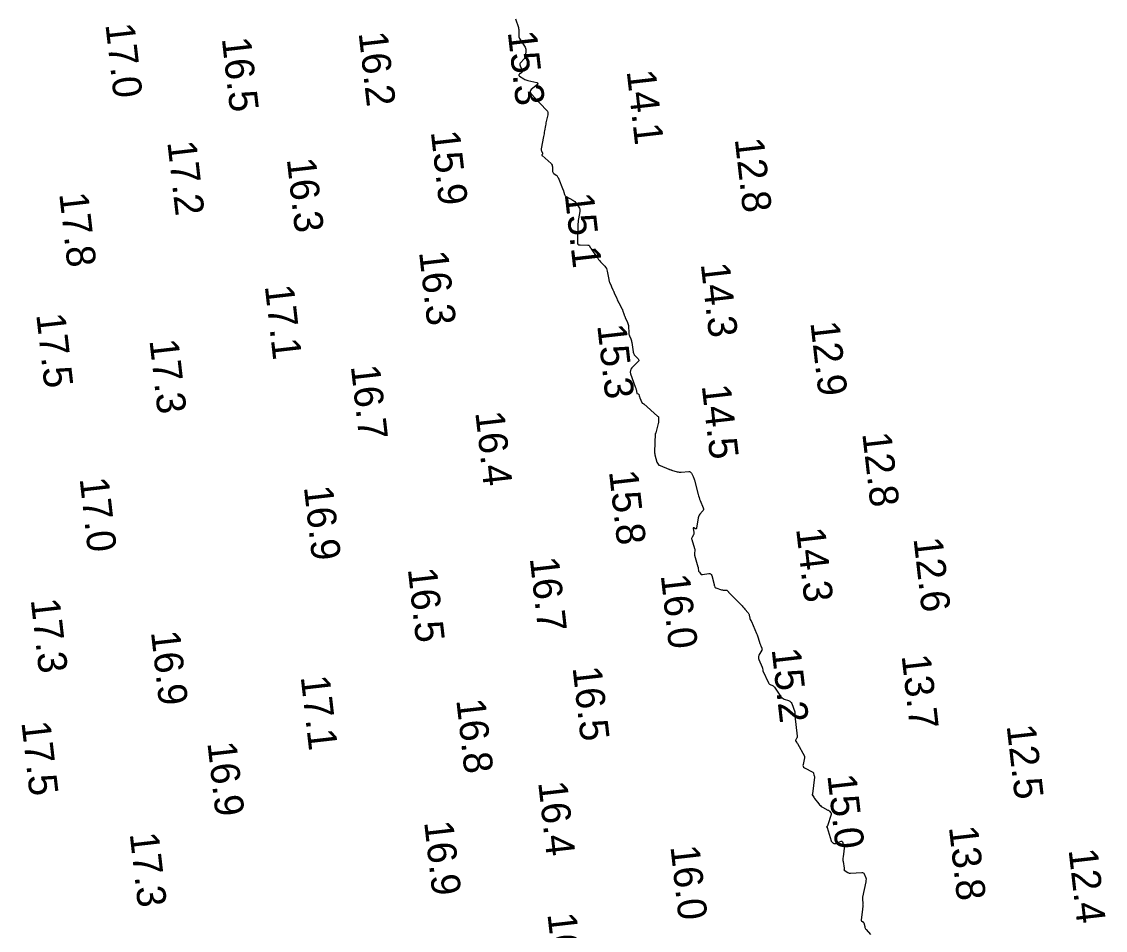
# Model space of a CAD drawing. Extents: x 1023796 to 1112670, y 656573 to 837340.
# Drawn here: x 1110573.1 to 1110760.3, y 679399.9 to 679556.8 of the extents above; entities that cross this region are included whole.
import ezdxf

# ---------------------------------------------------------------- set-up
doc = ezdxf.new("R2010")
doc.units = 0
doc.layers.add('V-CHAN-CONT-15FT', color=7, linetype='Continuous')
doc.layers.add('V-TOPO-SOUN', color=7, linetype='Continuous')

msp = doc.modelspace()

# ---------------------------------------------------------------- linework, layer by layer
at = {"layer": 'V-CHAN-CONT-15FT'}
msp.add_lwpolyline([(1110658.4, 679557.31), (1110658.91, 679555.84), (1110658.96, 679555.67), (1110659, 679555.5), (1110659.01, 679555.32), (1110659.02, 679555.14), (1110659, 679554.42), (1110659.01, 679554.25), (1110659.04, 679554.08), (1110659.11, 679553.92), (1110659.2, 679553.77), (1110660, 679552.63), (1110660.1, 679552.45), (1110660.17, 679552.27), (1110660.21, 679552.07), (1110660.22, 679551.87), (1110660.17, 679550.99), (1110660.15, 679550.81), (1110660.09, 679550.64), (1110660, 679550.49), (1110659.88, 679550.35), (1110659.34, 679549.82), (1110659.23, 679549.68), (1110659.18, 679549.54), (1110659.17, 679549.38), (1110659.22, 679549.22), (1110659.58, 679548.44), (1110659.61, 679548.33), (1110659.61, 679548.23), (1110659.57, 679548.14), (1110659.49, 679548.06), (1110659.09, 679547.75), (1110659.01, 679547.67), (1110658.99, 679547.6), (1110659.02, 679547.53), (1110659.1, 679547.46), (1110659.85, 679546.98), (1110660.01, 679546.88), (1110660.18, 679546.8), (1110660.36, 679546.74), (1110660.54, 679546.69), (1110662.08, 679546.35), (1110662.11, 679546.34), (1110662.14, 679546.32), (1110662.17, 679546.3), (1110662.19, 679546.26), (1110662.25, 679546.12), (1110662.26, 679546.09), (1110662.26, 679546.06), (1110662.24, 679546.03), (1110662.22, 679546), (1110661.14, 679545.13), (1110661, 679544.97), (1110660.94, 679544.81), (1110660.97, 679544.64), (1110661.09, 679544.46), (1110661.95, 679543.5), (1110662.15, 679543.28), (1110662.35, 679543.06), (1110662.55, 679542.85), (1110662.75, 679542.63), (1110663.79, 679541.54), (1110663.92, 679541.36), (1110664, 679541.17), (1110664.03, 679540.97), (1110664, 679540.75), (1110663.78, 679539.84), (1110663.73, 679539.61), (1110663.68, 679539.39), (1110663.63, 679539.16), (1110663.59, 679538.93), (1110663.43, 679537.97), (1110663.39, 679537.74), (1110663.35, 679537.5), (1110663.31, 679537.27), (1110663.26, 679537.03), (1110662.86, 679534.89), (1110662.85, 679534.8), (1110662.85, 679534.71), (1110662.87, 679534.63), (1110662.9, 679534.54), (1110663.09, 679534.12), (1110663.11, 679534.08), (1110663.11, 679534.05), (1110663.1, 679534.01), (1110663.08, 679533.98), (1110662.98, 679533.85), (1110662.97, 679533.82), (1110662.96, 679533.79), (1110662.97, 679533.76), (1110663, 679533.74), (1110664.55, 679532.34), (1110664.65, 679532.22), (1110664.73, 679532.09), (1110664.78, 679531.94), (1110664.8, 679531.79), (1110664.81, 679531.06), (1110664.82, 679530.94), (1110664.87, 679530.83), (1110664.93, 679530.73), (1110665.03, 679530.65), (1110665.45, 679530.35), (1110665.55, 679530.27), (1110665.63, 679530.17), (1110665.7, 679530.07), (1110665.76, 679529.96), (1110666.64, 679527.76), (1110666.68, 679527.67), (1110666.72, 679527.57), (1110666.75, 679527.47), (1110666.78, 679527.37), (1110666.9, 679526.97), (1110666.94, 679526.87), (1110666.99, 679526.79), (1110667.06, 679526.72), (1110667.15, 679526.66), (1110668.32, 679525.99), (1110668.49, 679525.88), (1110668.64, 679525.76), (1110668.78, 679525.61), (1110668.9, 679525.46), (1110669.36, 679524.8), (1110669.45, 679524.63), (1110669.51, 679524.45), (1110669.54, 679524.27), (1110669.52, 679524.07), (1110669.3, 679522.77), (1110669.26, 679522.49), (1110669.22, 679522.2), (1110669.2, 679521.92), (1110669.19, 679521.63), (1110669.1, 679518.8), (1110669.12, 679518.58), (1110669.21, 679518.42), (1110669.37, 679518.32), (1110669.58, 679518.29), (1110670.93, 679518.26), (1110671.01, 679518.25), (1110671.07, 679518.23), (1110671.12, 679518.19), (1110671.17, 679518.13), (1110671.34, 679517.87), (1110671.38, 679517.8), (1110671.42, 679517.74), (1110671.46, 679517.68), (1110671.51, 679517.61), (1110672.47, 679516.2), (1110672.62, 679515.99), (1110672.78, 679515.78), (1110672.94, 679515.58), (1110673.12, 679515.39), (1110673.83, 679514.63), (1110673.99, 679514.44), (1110674.12, 679514.22), (1110674.21, 679513.99), (1110674.27, 679513.75), (1110674.51, 679512.34), (1110674.54, 679512.22), (1110674.57, 679512.1), (1110674.61, 679511.98), (1110674.65, 679511.87), (1110674.89, 679511.33), (1110674.92, 679511.26), (1110674.95, 679511.19), (1110674.98, 679511.13), (1110675.01, 679511.06), (1110675.14, 679510.77), (1110675.17, 679510.71), (1110675.19, 679510.65), (1110675.22, 679510.59), (1110675.25, 679510.53), (1110675.36, 679510.28), (1110675.39, 679510.22), (1110675.41, 679510.15), (1110675.44, 679510.09), (1110675.47, 679510.03), (1110675.9, 679509.02), (1110675.98, 679508.83), (1110676.07, 679508.65), (1110676.16, 679508.46), (1110676.25, 679508.28), (1110676.82, 679507.21), (1110676.87, 679507.12), (1110676.91, 679507.03), (1110676.95, 679506.93), (1110676.98, 679506.84), (1110677.12, 679506.37), (1110677.14, 679506.31), (1110677.16, 679506.26), (1110677.18, 679506.21), (1110677.2, 679506.15), (1110677.28, 679505.95), (1110677.3, 679505.89), (1110677.33, 679505.84), (1110677.35, 679505.79), (1110677.37, 679505.74), (1110677.77, 679504.88), (1110677.83, 679504.72), (1110677.88, 679504.55), (1110677.91, 679504.38), (1110677.93, 679504.21), (1110677.97, 679503.18), (1110677.99, 679503.03), (1110678.01, 679502.88), (1110678.05, 679502.74), (1110678.1, 679502.6), (1110678.33, 679502.04), (1110678.38, 679501.9), (1110678.43, 679501.75), (1110678.46, 679501.61), (1110678.49, 679501.46), (1110678.72, 679499.85), (1110678.73, 679499.79), (1110678.74, 679499.72), (1110678.77, 679499.66), (1110678.79, 679499.6), (1110678.91, 679499.36), (1110678.94, 679499.3), (1110678.97, 679499.24), (1110679.01, 679499.19), (1110679.06, 679499.14), (1110679.6, 679498.61), (1110679.68, 679498.5), (1110679.71, 679498.39), (1110679.69, 679498.29), (1110679.61, 679498.18), (1110678.53, 679497.07), (1110678.35, 679496.84), (1110678.26, 679496.59), (1110678.24, 679496.33), (1110678.3, 679496.05), (1110679.11, 679493.78), (1110679.15, 679493.67), (1110679.18, 679493.56), (1110679.21, 679493.44), (1110679.24, 679493.32), (1110679.35, 679492.68), (1110679.37, 679492.65), (1110679.38, 679492.62), (1110679.41, 679492.61), (1110679.44, 679492.6), (1110679.59, 679492.57), (1110679.62, 679492.56), (1110679.65, 679492.54), (1110679.67, 679492.52), (1110679.69, 679492.49), (1110679.8, 679492.16), (1110679.82, 679492.09), (1110679.84, 679492.03), (1110679.87, 679491.96), (1110679.9, 679491.89), (1110680.24, 679491.05), (1110680.25, 679491.02), (1110680.27, 679491), (1110680.3, 679490.98), (1110680.32, 679490.97), (1110680.45, 679490.92), (1110680.47, 679490.91), (1110680.5, 679490.89), (1110680.53, 679490.87), (1110680.56, 679490.85), (1110682.96, 679488.74), (1110683.03, 679488.66), (1110683.09, 679488.57), (1110683.12, 679488.47), (1110683.13, 679488.36), (1110683.12, 679487.9), (1110683.12, 679487.79), (1110683.11, 679487.67), (1110683.09, 679487.56), (1110683.07, 679487.45), (1110682.67, 679485.82), (1110682.66, 679485.8), (1110682.65, 679485.79), (1110682.64, 679485.77), (1110682.63, 679485.76), (1110682.57, 679485.71), (1110682.56, 679485.69), (1110682.55, 679485.68), (1110682.54, 679485.66), (1110682.54, 679485.64), (1110682.42, 679482.55), (1110682.42, 679482.52), (1110682.42, 679482.5), (1110682.42, 679482.47), (1110682.42, 679482.44), (1110682.43, 679482.29), (1110682.43, 679482.28), (1110682.43, 679482.28), (1110682.44, 679482.28), (1110682.44, 679482.27), (1110682.46, 679482.26), (1110682.47, 679482.25), (1110682.47, 679482.25), (1110682.47, 679482.24), (1110682.47, 679482.24), (1110682.49, 679482.13), (1110682.5, 679482.11), (1110682.5, 679482.09), (1110682.51, 679482.07), (1110682.51, 679482.05), (1110682.85, 679480.78), (1110682.93, 679480.58), (1110683.04, 679480.41), (1110683.2, 679480.27), (1110683.39, 679480.17), (1110684.91, 679479.56), (1110684.95, 679479.54), (1110684.99, 679479.53), (1110685.02, 679479.52), (1110685.06, 679479.5), (1110685.23, 679479.46), (1110685.27, 679479.45), (1110685.31, 679479.44), (1110685.35, 679479.43), (1110685.38, 679479.41), (1110686.34, 679479.12), (1110686.52, 679479.08), (1110686.69, 679479.05), (1110686.87, 679479.04), (1110687.05, 679479.04), (1110688.33, 679479.14), (1110688.48, 679479.13), (1110688.61, 679479.09), (1110688.72, 679479), (1110688.8, 679478.87), (1110689.09, 679478.29), (1110689.16, 679478.14), (1110689.22, 679477.99), (1110689.27, 679477.84), (1110689.32, 679477.68), (1110689.96, 679475.21), (1110690.04, 679474.93), (1110690.12, 679474.66), (1110690.22, 679474.4), (1110690.32, 679474.13), (1110690.84, 679472.89), (1110690.89, 679472.73), (1110690.88, 679472.58), (1110690.84, 679472.43), (1110690.74, 679472.3), (1110690.26, 679471.76), (1110690.15, 679471.62), (1110690.06, 679471.47), (1110690, 679471.31), (1110689.96, 679471.14), (1110689.68, 679469.37), (1110689.66, 679469.3), (1110689.62, 679469.26), (1110689.57, 679469.25), (1110689.5, 679469.27), (1110689.2, 679469.42), (1110689.13, 679469.44), (1110689.09, 679469.43), (1110689.08, 679469.39), (1110689.08, 679469.33), (1110689.22, 679468.65), (1110689.23, 679468.53), (1110689.22, 679468.43), (1110689.2, 679468.32), (1110689.15, 679468.22), (1110688.91, 679467.81), (1110688.87, 679467.71), (1110688.84, 679467.61), (1110688.84, 679467.5), (1110688.87, 679467.39), (1110689.35, 679465.85), (1110689.37, 679465.76), (1110689.38, 679465.66), (1110689.39, 679465.57), (1110689.38, 679465.47), (1110689.33, 679465.09), (1110689.32, 679465), (1110689.32, 679464.9), (1110689.33, 679464.81), (1110689.35, 679464.71), (1110689.92, 679462.68), (1110689.94, 679462.61), (1110689.95, 679462.54), (1110689.96, 679462.47), (1110689.97, 679462.4), (1110690, 679462.03), (1110690.01, 679462), (1110690.01, 679461.97), (1110690.03, 679461.95), (1110690.04, 679461.93), (1110690.12, 679461.84), (1110690.16, 679461.8), (1110690.19, 679461.75), (1110690.45, 679461.44), (1110690.5, 679461.39), (1110690.56, 679461.36), (1110690.63, 679461.35), (1110690.7, 679461.35), (1110691.78, 679461.51), (1110691.97, 679461.52), (1110692.12, 679461.46), (1110692.23, 679461.34), (1110692.3, 679461.17), (1110692.7, 679459.63), (1110692.71, 679459.57), (1110692.73, 679459.52), (1110692.75, 679459.46), (1110692.77, 679459.4), (1110692.87, 679459.19), (1110692.9, 679459.14), (1110692.93, 679459.1), (1110692.98, 679459.06), (1110693.03, 679459.04), (1110694.02, 679458.73), (1110694.11, 679458.7), (1110694.19, 679458.69), (1110694.28, 679458.68), (1110694.37, 679458.68), (1110694.8, 679458.68), (1110694.84, 679458.68), (1110694.89, 679458.66), (1110694.93, 679458.64), (1110694.96, 679458.61), (1110695.09, 679458.47), (1110695.13, 679458.43), (1110695.16, 679458.39), (1110695.2, 679458.36), (1110695.23, 679458.32), (1110697.56, 679455.95), (1110697.68, 679455.81), (1110697.81, 679455.68), (1110697.93, 679455.54), (1110698.05, 679455.4), (1110698.61, 679454.72), (1110698.67, 679454.64), (1110698.72, 679454.55), (1110698.75, 679454.45), (1110698.78, 679454.35), (1110698.88, 679453.83), (1110698.89, 679453.78), (1110698.9, 679453.72), (1110698.93, 679453.67), (1110698.95, 679453.62), (1110699.06, 679453.42), (1110699.09, 679453.37), (1110699.11, 679453.32), (1110699.14, 679453.27), (1110699.16, 679453.22), (1110700.06, 679451.16), (1110700.14, 679450.97), (1110700.21, 679450.78), (1110700.28, 679450.59), (1110700.34, 679450.4), (1110700.64, 679449.44), (1110700.67, 679449.34), (1110700.71, 679449.24), (1110700.74, 679449.14), (1110700.78, 679449.04), (1110700.95, 679448.65), (1110700.98, 679448.56), (1110700.99, 679448.46), (1110700.97, 679448.37), (1110700.94, 679448.28), (1110700.46, 679447.41), (1110700.39, 679447.23), (1110700.36, 679447.05), (1110700.37, 679446.87), (1110700.43, 679446.69), (1110701.02, 679445.36), (1110701.04, 679445.31), (1110701.06, 679445.25), (1110701.07, 679445.2), (1110701.08, 679445.14), (1110701.11, 679444.91), (1110701.11, 679444.86), (1110701.13, 679444.8), (1110701.14, 679444.75), (1110701.16, 679444.7), (1110702.09, 679442.65), (1110702.14, 679442.56), (1110702.21, 679442.48), (1110702.29, 679442.41), (1110702.38, 679442.36), (1110702.8, 679442.2), (1110702.9, 679442.15), (1110702.98, 679442.09), (1110703.06, 679442.02), (1110703.13, 679441.93), (1110704.21, 679440.33), (1110704.33, 679440.18), (1110704.48, 679440.04), (1110704.64, 679439.94), (1110704.82, 679439.86), (1110705.59, 679439.58), (1110705.77, 679439.5), (1110705.92, 679439.38), (1110706.03, 679439.24), (1110706.12, 679439.06), (1110706.65, 679437.65), (1110706.67, 679437.59), (1110706.68, 679437.54), (1110706.68, 679437.48), (1110706.68, 679437.42), (1110706.66, 679437.19), (1110706.65, 679437.13), (1110706.65, 679437.07), (1110706.66, 679437.01), (1110706.66, 679436.95), (1110707.08, 679433.46), (1110707.09, 679433.37), (1110707.07, 679433.29), (1110707.05, 679433.22), (1110707.01, 679433.14), (1110706.81, 679432.82), (1110706.78, 679432.77), (1110706.77, 679432.71), (1110706.78, 679432.66), (1110706.81, 679432.6), (1110706.96, 679432.39), (1110707, 679432.33), (1110707.03, 679432.28), (1110707.07, 679432.22), (1110707.1, 679432.16), (1110708.31, 679429.97), (1110708.32, 679429.95), (1110708.33, 679429.93), (1110708.33, 679429.9), (1110708.34, 679429.88), (1110708.35, 679429.78), (1110708.35, 679429.75), (1110708.35, 679429.73), (1110708.35, 679429.7), (1110708.34, 679429.68), (1110708.07, 679428.57), (1110708.05, 679428.39), (1110708.09, 679428.24), (1110708.18, 679428.11), (1110708.33, 679428), (1110709.74, 679427.24), (1110709.79, 679427.21), (1110709.84, 679427.16), (1110709.87, 679427.11), (1110709.89, 679427.04), (1110709.95, 679426.7), (1110709.96, 679426.67), (1110709.97, 679426.65), (1110709.98, 679426.62), (1110709.99, 679426.6), (1110710.05, 679426.5), (1110710.06, 679426.47), (1110710.07, 679426.45), (1110710.07, 679426.42), (1110710.07, 679426.39), (1110709.7, 679423.49), (1110709.7, 679423.48), (1110709.69, 679423.46), (1110709.69, 679423.45), (1110709.68, 679423.44), (1110709.64, 679423.38), (1110709.63, 679423.37), (1110709.63, 679423.36), (1110709.63, 679423.35), (1110709.64, 679423.34), (1110709.68, 679423.27), (1110709.7, 679423.24), (1110709.92, 679422.91), (1110709.96, 679422.85), (1110710, 679422.79), (1110710.04, 679422.74), (1110710.08, 679422.68), (1110710.78, 679421.75), (1110710.92, 679421.59), (1110711.07, 679421.45), (1110711.23, 679421.32), (1110711.41, 679421.21), (1110712.37, 679420.69), (1110712.45, 679420.64), (1110712.52, 679420.59), (1110712.59, 679420.53), (1110712.65, 679420.47), (1110712.88, 679420.2), (1110712.93, 679420.13), (1110712.95, 679420.06), (1110712.96, 679419.98), (1110712.94, 679419.9), (1110712.3, 679417.98), (1110712.29, 679417.95), (1110712.28, 679417.93), (1110712.26, 679417.9), (1110712.25, 679417.88), (1110712.15, 679417.75), (1110712.15, 679417.74), (1110712.15, 679417.74), (1110712.15, 679417.73), (1110712.16, 679417.72), (1110712.2, 679417.7), (1110712.22, 679417.7), (1110712.22, 679417.69), (1110712.23, 679417.68), (1110712.23, 679417.67), (1110712.93, 679415.39), (1110712.95, 679415.33), (1110712.98, 679415.28), (1110713.01, 679415.24), (1110713.05, 679415.19), (1110713.21, 679415.01), (1110713.25, 679414.98), (1110713.29, 679414.95), (1110713.34, 679414.94), (1110713.39, 679414.93), (1110713.61, 679414.92), (1110713.66, 679414.92), (1110713.71, 679414.92), (1110713.76, 679414.93), (1110713.81, 679414.95), (1110714.67, 679415.31), (1110714.74, 679415.32), (1110714.8, 679415.31), (1110714.84, 679415.28), (1110714.88, 679415.21), (1110715.01, 679414.79), (1110715.02, 679414.76), (1110715.04, 679414.73), (1110715.06, 679414.71), (1110715.08, 679414.69), (1110715.2, 679414.63), (1110715.22, 679414.61), (1110715.24, 679414.59), (1110715.24, 679414.57), (1110715.24, 679414.54), (1110714.98, 679412.59), (1110714.96, 679412.39), (1110714.96, 679412.19), (1110714.97, 679411.99), (1110715, 679411.79), (1110715.19, 679410.67), (1110715.19, 679410.64), (1110715.19, 679410.6), (1110715.19, 679410.57), (1110715.18, 679410.54), (1110715.15, 679410.41), (1110715.14, 679410.37), (1110715.15, 679410.35), (1110715.16, 679410.32), (1110715.19, 679410.3), (1110715.81, 679409.9), (1110715.92, 679409.84), (1110716.04, 679409.8), (1110716.17, 679409.77), (1110716.3, 679409.77), (1110718.24, 679409.89), (1110718.37, 679409.88), (1110718.48, 679409.84), (1110718.57, 679409.76), (1110718.64, 679409.65), (1110718.92, 679408.95), (1110718.94, 679408.9), (1110718.95, 679408.84), (1110718.96, 679408.79), (1110718.96, 679408.73), (1110718.94, 679408.51), (1110718.93, 679408.45), (1110718.93, 679408.4), (1110718.92, 679408.34), (1110718.91, 679408.29), (1110718.35, 679405.62), (1110718.35, 679405.6), (1110718.35, 679405.58), (1110718.35, 679405.56), (1110718.35, 679405.54), (1110718.36, 679405.46), (1110718.36, 679405.44), (1110718.36, 679405.42), (1110718.36, 679405.4), (1110718.36, 679405.38), (1110718.43, 679404.45), (1110718.44, 679404.38), (1110718.43, 679404.3), (1110718.43, 679404.22), (1110718.42, 679404.14), (1110718.38, 679403.83), (1110718.37, 679403.75), (1110718.36, 679403.68), (1110718.35, 679403.6), (1110718.34, 679403.52), (1110718.11, 679401.71), (1110718.11, 679401.66), (1110718.12, 679401.6), (1110718.15, 679401.56), (1110718.2, 679401.53), (1110718.41, 679401.4), (1110718.46, 679401.37), (1110718.5, 679401.32), (1110718.53, 679401.27), (1110718.55, 679401.22), (1110718.73, 679400.55), (1110718.77, 679400.42), (1110718.82, 679400.3), (1110718.89, 679400.18), (1110718.98, 679400.08), (1110719.75, 679399.2)], dxfattribs=at)

# ---------------------------------------------------------------- texts
at = {"layer": 'V-TOPO-SOUN'}
for s, p in [('17.0 ', (1110587.59, 679556.37)), ('16.2 ', (1110631.31, 679554.92)), ('15.3 ', (1110657.07, 679555.06)), ('16.5 ', (1110607.69, 679553.95)), ('14.1 ', (1110677.61, 679548.3)), ('17.2 ', (1110598.28, 679536.06)), ('15.9 ', (1110643.78, 679537.83)), ('12.8 ', (1110696.27, 679536.58)), ('16.3 ', (1110618.91, 679533.11)), ('17.8 ', (1110579.61, 679527.14)), ('15.1 ', (1110666.91, 679527.04)), ('16.3 ', (1110641.75, 679517.06)), ('14.3 ', (1110690.4, 679515)), ('17.1 ', (1110615.11, 679511.19)), ('17.5 ', (1110575.64, 679506.28)), ('15.3 ', (1110672.52, 679504.4)), ('12.9 ', (1110709.33, 679504.89)), ('17.3 ', (1110595.19, 679501.81)), ('16.7 ', (1110629.97, 679497.35)), ('14.5 ', (1110690.57, 679493.98)), ('16.4 ', (1110651.46, 679489.37)), ('12.8 ', (1110718.29, 679485.73)), ('15.8 ', (1110674.55, 679479.17)), ('17.0 ', (1110583.13, 679477.93)), ('16.9 ', (1110621.86, 679476.48)), ('14.3 ', (1110706.87, 679469.26)), ('12.6 ', (1110727.14, 679467.58)), ('16.7 ', (1110660.87, 679464.18)), ('16.5 ', (1110639.81, 679462.32)), ('16.0 ', (1110683.49, 679461.23)), ('17.3 ', (1110574.69, 679457.02)), ('16.9 ', (1110595.45, 679451.45)), ('15.2 ', (1110702.64, 679448.46)), ('13.7 ', (1110725.08, 679447.35)), ('16.5 ', (1110668.26, 679445.29)), ('17.1 ', (1110621.31, 679443.71)), ('16.8 ', (1110648.18, 679439.7)), ('17.5 ', (1110573.08, 679435.84)), ('12.5 ', (1110743.22, 679435.25)), ('16.9 ', (1110605.2, 679432.29)), ('15.0 ', (1110712.26, 679426.68)), ('16.4 ', (1110662.32, 679425.46)), ('16.9 ', (1110642.63, 679418.61)), ('17.3 ', (1110591.78, 679416.6)), ('13.8 ', (1110733.25, 679417.75)), ('16.0 ', (1110685.16, 679414.38)), ('12.4 ', (1110753.92, 679413.82)), ('16.3 ', (1110663.92, 679402.73))]:
    msp.add_text(s, height=5, rotation=276.5594, dxfattribs=at).set_placement(p)

doc.saveas('drawing.dxf')
